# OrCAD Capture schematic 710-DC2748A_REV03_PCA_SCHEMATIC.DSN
size B; rev: 03; note: DEMO CIRTCUIT DC2748A; note: IN A 2x2 LQFN
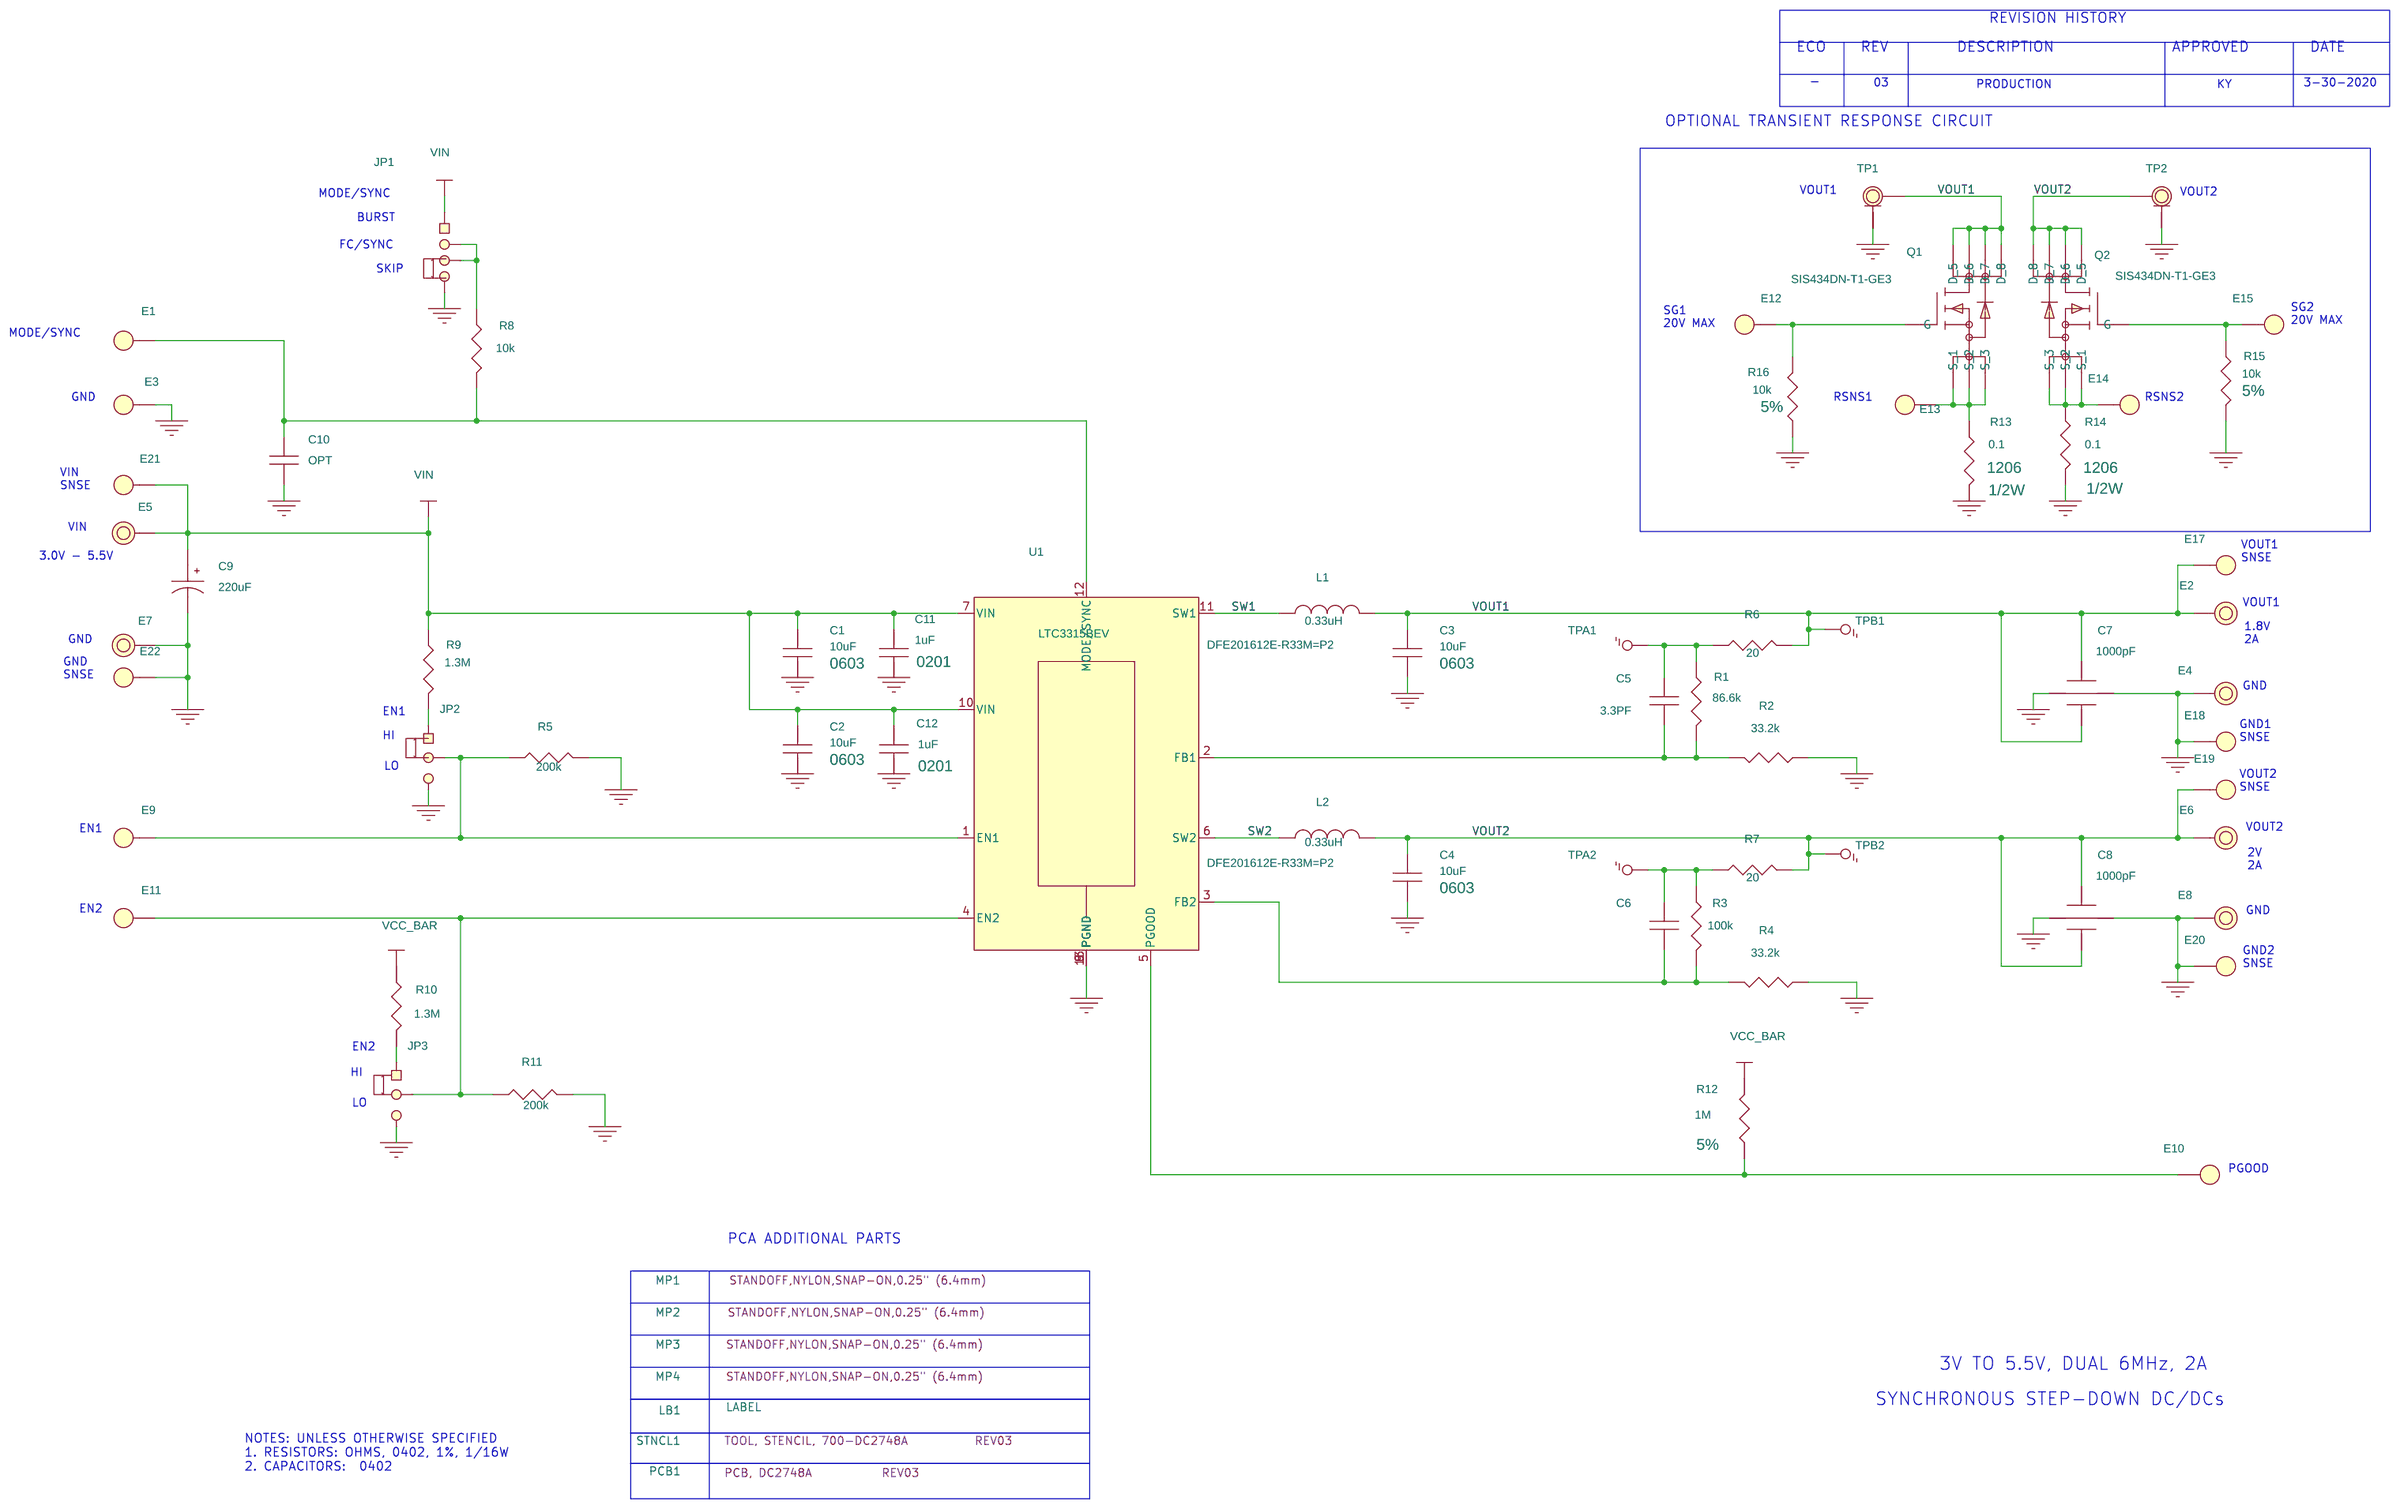
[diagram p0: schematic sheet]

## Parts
C1  10uF  [CC0603N]
C2  10uF  [CC0603N]
C3  10uF  [CC0603N]
C4  10uF  [CC0603N]
C5  3.3PF  [CC0402N]
C6  3.3PF  [CC0402N]
C7  1000pF  [JOHANSON-X2Y-X07]
C8  1000pF  [JOHANSON-X2Y-X07]
C9  220uF  [CAPMP7343N]
C10  OPT  [CC0402N]
C11  1uF  [CC0201M]
C12  1uF  [CC0201M]
E1  TEST POINT  [MILLMAX2308]
E2  TEST POINT  [MILLMAX2501]
E3  TEST POINT  [MILLMAX2308]
E4  TEST POINT  [MILLMAX2501]
E5  TEST POINT  [MILLMAX2501]
E6  TEST POINT  [MILLMAX2501]
E7  TEST POINT  [MILLMAX2501]
E8  TEST POINT  [MILLMAX2501]
E9  TEST POINT  [MILLMAX2308]
E10  TEST POINT  [MILLMAX2308]
E11  TEST POINT  [MILLMAX2308]
E12  TEST POINT  [MILLMAX2308]
E13  TEST POINT  [MILLMAX2308]
E14  TEST POINT  [MILLMAX2308]
E15  TEST POINT  [MILLMAX2308]
E17  TEST POINT  [MILLMAX2308]
E18  TEST POINT  [MILLMAX2308]
E19  TEST POINT  [MILLMAX2308]
E20  TEST POINT  [MILLMAX2308]
E21  TEST POINT  [MILLMAX2308]
E22  TEST POINT  [MILLMAX2308]
JP1  HDR  [JP4X1/079]
JP2  HDR  [HD1X3-079]
JP3  HDR  [HD1X3-079]
L1  0.33uH  [MURATA-DFE201612E]
L2  0.33uH  [MURATA-DFE201612E]
LB1  LABEL  [895-0154_REV01]
MP1  STANDOFF  [KEYSTONE_8829-8834]
MP2  STANDOFF  [KEYSTONE_8829-8834]
MP3  STANDOFF  [KEYSTONE_8829-8834]
MP4  STANDOFF  [KEYSTONE_8829-8834]
PCB1  PCB, DC2748A
Q1  SIS434DN-T1-GE3  [VISHAY-POWERPAK1212-8S]
Q2  SIS434DN-T1-GE3  [VISHAY-POWERPAK1212-8S]
R1  86.6k  [CR0402N]
R2  33.2k  [CR0402N]
R3  100k  [CR0402N]
R4  33.2k  [CR0402N]
R5  200k  [CR0402N]
R6  20  [CR0402N]
R7  20  [CR0402N]
R8  10k  [CR0402N]
R9  1.3M  [CR0402N]
R10  1.3M  [CR0402N]
R11  200k  [CR0402N]
R12  1M  [CR0402N]
R13  0.1  [CR1206N]
R14  0.1  [CR1206N]
R15  10k  [CR0402N]
R16  10k  [CR0402N]
STNCL1  TOOL, STENCIL, 700-DC2748A
TP1  U.FL  [HIROSE-FL-R-SMT-1]
TP2  U.FL  [HIROSE-FL-R-SMT-1]
TPA1  COPPER FEATURE PAD  [PADSTYLE1]
TPA2  COPPER FEATURE PAD  [PADSTYLE1]
TPB1  COPPER FEATURE PAD  [PADSTYLE1]
TPB2  COPPER FEATURE PAD  [PADSTYLE1]
U1  LTC3315BEV  [LTC-LQFN-12-1530]
XJP1  SHUNT
XJP2  SHUNT
XJP3  SHUNT

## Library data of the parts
C1-C4 = CAP: CAP.,10uF,X7S,6.3V,20%,0603; CLASS: DISCRETE; Dielectric Type: X7S; FPLIST: CC0603N,CC0603L,CC0603M; Inventory Qty: 29400; Manufacturer: TDK; Manufacturer PN: C1608X7S0J106M080AC; PART_NUMBER: 150-1745; Package Size: 0603; Rated Voltage: 6.3V; Tolerance: 20%
C5 C6 = CAP: CAP.,3.3PF,C0G,50V,0.25pF,0402; CLASS: DISCRETE; Dielectric Type: C0G; FPLIST: CC0402N,CC0402L,CC0402M; Inventory Qty: 19700; Manufacturer: AVX; Manufacturer PN: 04025A3R3CAT2A; PART_NUMBER: 150-2077; Package Size: 0402; Rated Voltage: 50V; Tolerance: 0.25pF
C7 C8 = JOHANSON-X2Y: CAP.,1000pF,X7R,50V,20%,0402,3-TERM,X2Y EMI FILTER; CLASS: DISCRETE; Dielectric Type: X7R; Inventory Qty: 15300; Manufacturer: JOHANSON DIELECTRICS; Manufacturer PN: 500X07W102MV4T; PART_NUMBER: 150-1785; Package Size: 0402,3-TERM; Rated Voltage: 50V; Tolerance: 20%
C9 = CAP_P_ALT: CAP.,220uF,TANT. POSCAP,6.3V,20%,7343,18mOHMS, TPE, NO SUBS. ALLOWED; CLASS: DISCRETE; Dielectric Type: TANT. POSCAP; FPLIST: CAPMP7343N,CAPMP7343L,CAPMP7343N; Inventory Qty: 3500; Manufacturer: PANASONIC; Manufacturer PN: 6TPE220MI; PART_NUMBER: 150-3532; Package Size: 7343; Rated Voltage: 6.3V; Tolerance: 20%
C10 = CAP: CAP., OPTION, 0402; CLASS: DISCRETE; PART_NUMBER: 150-3148; Package Size: 0402; Package Type: SMD
C11 C12 = CAP: CAP.,1uF,X7T,6.3V,20%,0201; CLASS: DISCRETE; Dielectric Type: X7T; FPLIST: CC0201N,CC0201L,CC0201M; Inventory Qty: 400; Manufacturer: MURATA; Manufacturer PN: GRM033D70J105ME01D; PART_NUMBER: 150-1771; Package Size: 0201; Rated Voltage: 6.3V; Tolerance: 20%
E1 E3 E9-E15 E17-E22 = TEST_POINT_.156_MILL-MAX_2308: TEST POINT,TURRET,0.064" MTG. HOLE,PCB 0.062" THK; CLASS: IO; Inventory Qty: 803450; Manufacturer PN: 2308-2-00-80-00-00-07-0; PART_NUMBER: 260-0004
E2 E4-E8 = TESTPOINT_.219_MILL-MAX_2501: TEST POINT,TURRET,0.094" MTG. HOLE,PCB 0.062" THK; CLASS: IO; Inventory Qty: 509305; Manufacturer: MILL-MAX; Manufacturer PN: 2501-2-00-80-00-00-07-0; PART_NUMBER: 260-0003
JP1 = HD1X4-079_ALT: CONN.,HDR,MALE,1x4,2mm,VERT,ST,THT; CLASS: IO; Inventory Qty: 10951; Manufacturer: WURTH ELEKTRONIK; Manufacturer PN: 62000411121; PART_NUMBER: 250-0563
JP2 JP3 = 3_PIN_HEADER_.079_SINGLE_ROW_D: CONN.,HDR,MALE,1x3,2mm,VERT,ST,THT; CLASS: IO; Inventory Qty: 23685; Manufacturer: Wurth Elektronik; Manufacturer PN: 62000311121; PART_NUMBER: 250-0484
L1 L2 = IND_ALT: IND.,0.33uH,PWR,FIXED,20%,6.3A,21mOHMS,0806; CLASS: DISCRETE; Inventory Qty: 700; Manufacturer: MURATA; Manufacturer PN: DFE201612E-R33M=P2; PART_NUMBER: 200-0372; Package Size: 0806; Tolerance: 20%
LB1 = BLANK_LABEL: LABEL SPEC, DEMO BOARD SERIAL NUMBER; Inventory Qty: 0; Manufacturer: BRADY; Manufacturer PN: THT-96-717-10; PART_NUMBER: 895-0154
MP1-MP4 = BLANK_MECHANICAL_PART: STANDOFF,NYLON,SNAP-ON,0.25" (6.4mm); CLASS: DISCRETE; FPLIST: KEYSTONE_8829-8834,MTG-8831; Inventory Qty: 203772; Manufacturer: KEYSTONE; Manufacturer PN: 8831; PART_NUMBER: 763-0006
PCB1 = BLANK_PCB_PART: BOM Notes: REV03; CLASS: DISCRETE; Inventory Qty: 0; Manufacturer: ADI APPROVED SUPPLIER; Manufacturer PN: 600-DC2748A; PART_NUMBER: 600-DC2748A
Q1 Q2 = 8P_N-CH_TYPE1A: XSTR.,MOSFET, N-CH,40V,35A,PowerPAK 1212-8; CLASS: DISCRETE; Inventory Qty: 1048; Manufacturer: Vishay; PART_NUMBER: 240-0280; Package Type: PowerPAK 1212-8; Rated Voltage: 40V
R1 = RES: RES.,86.6k OHMS,1%,1/16W,0402,AEC-Q200; CLASS: DISCRETE; FPLIST: CR0402N,CR0402L,CR0402M; Inventory Qty: 400; Manufacturer: NIC; Manufacturer PN: NRC04F8662TRF; PART_NUMBER: 100-1118; Package Size: 0402; Rated Power: 1/16W; Temperature Coefficient: 100ppm; Tolerance: 1%
R2 R4 = RES: RES.,33.2k OHMS,1%,1/16W,0402; CLASS: DISCRETE; FPLIST: CR0402N,CR0402L,CR0402M; Inventory Qty: 20821; Manufacturer: VISHAY; Manufacturer PN: CRCW040233K2FKED; PART_NUMBER: 100-2946; Package Size: 0402; Rated Power: 1/16W; Temperature Coefficient: 100ppm; Tolerance: 1%
R3 = RES: RES.,100k OHMS,1%,1/16W,0402,AEC-Q200; CLASS: DISCRETE; FPLIST: CR0402N,CR0402L,CR0402M; Inventory Qty: 153051; Manufacturer: VISHAY; Manufacturer PN: CRCW0402100KFKED; PART_NUMBER: 100-2396; Package Size: 0402; Rated Power: 1/16W; Temperature Coefficient: 100ppm; Tolerance: 1%
R5 R11 = RES: RES.,200k OHMS,1%,1/16W,0402; CLASS: DISCRETE; FPLIST: CR0402N,CR0402L,CR0402M; Inventory Qty: 78278; Manufacturer: NIC; Manufacturer PN: NRC04F2003TRF; PART_NUMBER: 100-0329; Package Size: 0402; Rated Power: 1/16W; Temperature Coefficient: 100ppm/C; Tolerance: 1%
R6 R7 = RES: RES.,20 OHMS,1%,1/16W,0402,AEC-Q200; CLASS: DISCRETE; FPLIST: CR0402N,CR0402L,CR0402M; Inventory Qty: 32095; Manufacturer: NIC; Manufacturer PN: NRC04F20R0TRF; PART_NUMBER: 100-0250; Package Size: 0402; Rated Power: 1/16W; Temperature Coefficient: 100ppm; Tolerance: 1%
R8 = RES: RES.,10k OHMS,5%,1/16W,0402,AEC-Q200; CLASS: DISCRETE; FPLIST: CR0402N,CR0402L,CR0402M; Inventory Qty: 69667; Manufacturer: NIC; Manufacturer PN: NRC04J103TRF; PART_NUMBER: 100-0214; Package Size: 0402; Rated Power: 1/16W; Temperature Coefficient: 200ppm; Tolerance: 5%
R9 R10 = RES: RES.,1.3M OHMS,1%,1/16W,0402; CLASS: DISCRETE; FPLIST: CR0402N,CR0402L,CR0402M; Inventory Qty: 0; Manufacturer: VISHAY; Manufacturer PN: CRCW04021M30FKED; PART_NUMBER: 100-2978; Package Size: 0402; Rated Power: 1/16W; Temperature Coefficient: +/-100; Tolerance: 1%
R12 = RES: RES.,1M OHM,5%,1/16W,0402,AEC-Q200; CLASS: DISCRETE; FPLIST: CR0402N,CR0402L,CR0402M; Inventory Qty: 26140; Manufacturer: VISHAY; Manufacturer PN: CRCW04021M00JNED; PART_NUMBER: 100-0321; Package Size: 0402; Rated Power: 1/16W; Temperature Coefficient: 200ppm; Tolerance: 5%
R13 R14 = RES: RES.,0.1 OHM,1%,1/2W,1206,SENSE,AEC-Q200; CLASS: DISCRETE; FPLIST: CR1206N,CR1206L,CR1206M; Inventory Qty: 2675; Manufacturer: IRC; Manufacturer PN: LRC-LR1206LF-01-R100-F; PART_NUMBER: 100-2842; Package Size: 1206; Rated Power: 1/2W; Temperature Coefficient: +/-100ppm; Tolerance: 1%
R15 R16 = RES: RES.,10k OHMS,5%,1/10W,0402,AEC-Q200; CLASS: DISCRETE; FPLIST: CR0402N,CR0402L,CR0402M; Inventory Qty: 33611; Manufacturer: PANASONIC; Manufacturer PN: ERJ2GEJ103X; PART_NUMBER: 100-0092; Package Size: 0402; Rated Power: 1/10W; Temperature Coefficient: 200ppm/C; Tolerance: 5%
STNCL1 = BLANK_STENCIL_PART: BOM Notes: REV03; CLASS: DISCRETE; Inventory Qty: 0; Manufacturer: ADI APPROVED SUPPLIER; Manufacturer PN: 830-DC2748A; PART_NUMBER: 830-DC2748A
TP1 TP2 = HIROSE-U.FL-R-SMT-1: CONN.,U.FL,RECEPT,ST SMD,0Hz to 6GHz 50Ohm; CLASS: IO; Inventory Qty: 0; Manufacturer: HIROSE ELECTRIC; Manufacturer PN: U.FL-R-SMT-1(10); PART_NUMBER: 250-0939
TPA1 TPA2 TPB1 TPB2 = PAD_SMALL_FILLED: TESTPOINT, PCB COPPER FEATURE; CLASS: IO; Manufacturer: N/A; Manufacturer PN: N/A; PART_NUMBER: PCBPADS-11
U1 = LTC3315BEV: IC,DUAL 5V,2A SYNCHRONOUS STEP-DOWN DC/DC,LQFN; CLASS: IC; Inventory Qty: 0; Manufacturer: ANALOG DEVICES; Manufacturer PN: LTC3315BEV#PBF; PART_NUMBER: LTC3315BEV#PBF; Package Size: 12-LGA; Package Type: LQFN
XJP1-XJP3 = CONN_SHUNT_2_POS_2mm: CONN.,SHUNT,FEMALE,2 POS,2mm; CLASS: IO; Inventory Qty: 67810; Manufacturer: Wurth Elektronik; Manufacturer PN: 60800213421; PART_NUMBER: 250-0485

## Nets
GND: C1.2 C2.2 C3.2 C4.2 C7.3(G1) C7.4(G2) C8.3(G1) C8.4(G2) C9.2 C10.2 C11.2 C12.2 E3.1(A) E4.1 E7.1 E8.1 E18.1(A) E20.1(A) E22.1(A) JP1.4 JP2.3 JP3.3 R2.1 R4.1 R5.2 R11.2 R13.2 R14.2 R15.2 R16.2 TP1.2(GND) TP1.3(GND) TP1.4(GND) TP1.5(GND) TP2.2(GND) TP2.3(GND) TP2.4(GND) TP2.5(GND) U1.8(PGND) U1.9(PGND) U1.13(PGND)
VIN: C1.1 C2.1 C9.1 C11.1 C12.1 E5.1 E21.1(A) JP1.1 R9.1 R10.1 R12.1 U1.7(VIN) U1.10(VIN)
SW1: L1.1 U1.11(SW1)
SW2: L2.1 U1.6(SW2)
VOUT1: C3.1 C7.1(A) C7.2(B) E2.1 E17.1(A) L1.2 Q1.5(D) Q1.6(D) Q1.7(D) Q1.8(D) R6.2 TP1.1 TPB1.1
VOUT2: C4.1 C8.1(A) C8.2(B) E6.1 E19.1(A) L2.2 Q2.5(D) Q2.6(D) Q2.7(D) Q2.8(D) R7.2 TP2.1 TPB2.1
N16681125: E10.1(A) R12.2 U1.5(PGOOD)
N16719202: C5.2 R1.2 R2.2 U1.2(FB1)
N16720569: E9.1(A) JP2.2 R5.1 U1.1(EN1)
N16755831: C5.1 R1.1 R6.1 TPA1.1
N16760018: JP2.1 R9.2
N16761514: C10.1 E1.1(A) R8.2 U1.12(MODE/SYNC)
N16782196: JP1.2 JP1.3 R8.1
N16868957: C6.1 R3.1 R7.1 TPA2.1
N16868970: C6.2 R3.2 R4.2 U1.3(FB2)
N16870961: E11.1(A) JP3.2 R11.1 U1.4(EN2)
N16871341: JP3.1 R10.2
N16897106: E12.1(A) Q1.4(G) R16.1
N16897112: E15.1(A) Q2.4(G) R15.1
N16897143: E13.1(A) Q1.1(S) Q1.2(S) Q1.3(S) R13.1
N16897149: E14.1(A) Q2.1(S) Q2.2(S) Q2.3(S) R14.1

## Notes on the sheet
- REVISION HISTORY
- ECO
- REV
- DESCRIPTION
- APPROVED
- DATE
- -
- 03
- PRODUCTION
- KY
- 3-30-2020
- OPTIONAL TRANSIENT RESPONSE CIRCUIT
- MODE/SYNC
- VOUT1
- VOUT2
- BURST
- FC/SYNC
- SKIP
- SG1
  20V MAX
- SG2
  20V MAX
- MODE/SYNC
- GND
- RSNS1
- RSNS2
- VIN
  SNSE
- VIN
- VOUT1
  SNSE
- 3.0V - 5.5V
- VOUT1
- GND
- 1.8V
  2A
- GND
  SNSE
- GND
- EN1
- GND1
  SNSE
- HI
- LO
- VOUT2
  SNSE
- EN1
- VOUT2
- 2V
  2A
- EN2
- GND
- GND2
  SNSE
- EN2
- HI
- LO
- PGOOD
- PCA ADDITIONAL PARTS
- 3V TO 5.5V, DUAL 6MHz, 2A
- SYNCHRONOUS STEP-DOWN DC/DCs
- NOTES: UNLESS OTHERWISE SPECIFIED
  1. RESISTORS: OHMS, 0402, 1%, 1/16W
  2. CAPACITORS:  0402
